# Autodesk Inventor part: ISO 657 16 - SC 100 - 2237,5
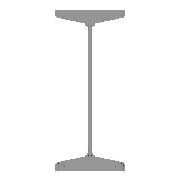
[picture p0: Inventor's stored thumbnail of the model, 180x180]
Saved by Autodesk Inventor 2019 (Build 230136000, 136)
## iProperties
_CCFamilyMember: 1
_CCFamilyDisplayName: ISO 657/16 - 1980 - Poutres en acier laminées à chaud - Partie 16: profilés en H (série métrique) - Cotes et propriétés de section
_FrameMemberDoc: Frame Member File
_Version: 15.0.0
_GetPNFromCC: 1
Created: 2018-07
Part Number: ISO 657 16 - SC 100 - 2237,5
Material: Acier, doux
Description: Poutres en acier laminées à chaud - Partie 16: profilés en H (série métrique) - Cotes et propriétés de section
Document SubType Name: Modeling
Standard: ISO
Designer: Fabian Perrée
Standard Revision: First edition 1980-02-15
Standards Organization: ISO
Language: fr-FR
Size Designation: SC 100
Categories: <MemberInstance><Categories><Category DisplayName="Profilés" InternalName="089c4875-fa83-4c05-b084-43b9cc11f5ed" Mnemonic="GRDR"><CategoryParameter DisplayName=
Stock Number: SC 100
Density: 7.85 g/cm^3
Appearance: Semi-poli
IsCustomPart: 1
G_W: 100,000 mm
G_H: 100,000 mm
+00612AE5-4A21-40A4-B490-CD8F624E81A5+DETAILDECOUPE1: Angle de coupe 90,00 deg
+1A323659-953F-4F35-8181-0827E3868009+DETAILDECOUPE2: Angle de coupe 67,38 deg
G_L: 2237,500 mm
Author: Fabian Perrée
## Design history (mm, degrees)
node "Plan de départ"
node "Plan de fin"
sketch "Esquisse"
  geometry: L1 (-3, 0)-(-3, -26.266); L2 (-13.33, -38.149)-(-44.835, -42.577); L3 (-50, -48.518)-(-50, -50); L4 (-50, -50)-(0, -50); L5 (-26.5, -50)-(-26.5, -40); L6 (-61.333, 0)-(81.777, 0); L7 (0, 0)-(0, -50); L8 (0, -60)-(0, 80); L9 (3, 0)-(3, -26.266); L10 (13.33, -38.149)-(44.835, -42.577); L11 (50, -48.518)-(50, -50); L12 (50, -50)-(0, -50); L13 (-3, 0)-(0, 0); L14 (-3, 0)-(-3, 26.266); L15 (-13.33, 38.149)-(-44.835, 42.577); L16 (-50, 48.518)-(-50, 50); L17 (-50, 50)-(0, 50); L18 (50, 48.518)-(50, 50); L19 (13.33, 38.149)-(44.835, 42.577); L20 (3, 0)-(3, 26.266); L21 (50, 50)-(0, 50); L22 (0, 108)-(0, -88) reference; L23 (-89.955, 0)-(110.399, 0) reference; A1 r 6 centre (-44, 48.518) between (-50, 48.518) and (-44.835, 42.577); A2 r 6 centre (44, 48.518) between (44.835, 42.577) and (50, 48.518); A3 r 6 centre (44, -48.518) between (50, -48.518) and (44.835, -42.577); A4 r 6 centre (-44, -48.518) between (-44.835, -42.577) and (-50, -48.518); A5 r 12 centre (-15, 26.266) between (-3, 26.266) and (-13.33, 38.149); A6 r 12 centre (15, 26.266) between (13.33, 38.149) and (3, 26.266); A7 r 12 centre (15, -26.266) between (3, -26.266) and (13.33, -38.149); A8 r 12 centre (-15, -26.266) between (-13.33, -38.149) and (-3, -26.266); 14 further points
  constraints: 42 end point, 24 point on line, 17 symmetric about line, 16 point on circle, 16 tangent, 8 centre point, 6 equal radius, 4 collinear, 2 perpendicular, 12 other
  dimensions: "d1" = 10 vertical distance of L3.end L5.end (= G_T1); "d2" = 23.5 distance between parallel lines of L5 L3 (= -0.25 x G_T + 0.25 x G_W); "d3" = 3 distance between parallel lines of L1 L7 (= 0.5 x G_T); "d4" = 50 distance between parallel lines of L7 L3 (= 0.5 x G_W); "d9" = 50 distance from line of L1.start L4 (= 0.5 x G_H); "d14" = 98 deg angle of L2 L1 (= G_NG); "d15" = 6 radius of A1 (= G_ER); "d16" = 12 radius of A5 (= G_IR)
extrude "Corps" new body sketch "Esquisse" stored distance "d5" = 2237.5 (= G_L); taper "d6" = 0 deg
node "Driven Length"
  sketch "Sketch3"
    geometry: L1 (0, 0)-(10, 0) reference
    constraints: 2 end point, 1 horizontal
  workplane "Work Plane3"
  sketch "Sketch4"
    geometry: L1 (-2, 87.5)-(12, 87.5) reference; L2 (-2, 2325)-(12, 2325) reference
    dimensions: "d20" = 2237.5 distance between parallel lines of L1 L2 (derived)
node "Plan de construction4"
feature "Scission1"
node "Plan de construction5"
feature "Scission2"
body "Solid1"
other parameters: "G_W" = 100 (= G_H) [user parameter; used in 2 equation terms], "G_H" = 100 [user parameter; used in 2 equation terms], "G_T" = 6 [user parameter; used in 2 equation terms], "G_T1" = 10 [user parameter; used in 1 equation term], "G_L" = 2237.5 (= d20) [user parameter; used in 1 equation term], "G_ER" = 6 [user parameter; used in 1 equation term], "G_IR" = 12 [user parameter; used in 1 equation term], "G_NG" = 98 deg [user parameter; used in 1 equation term], "G_OFFSET_START" = -87.5 [user parameter; used in 1 equation term], "d17" = 87.5 (= -G_OFFSET_START), "d18" = 2325 (= G_OFFSET_END + B_L), "B_L" = 2375 [user parameter; used in 1 equation term], "d19" = 90 deg
